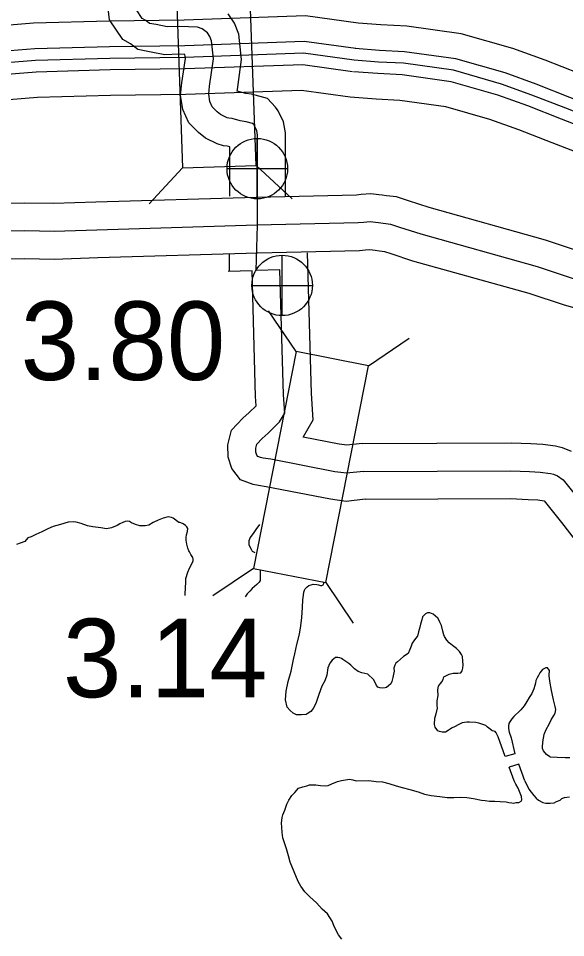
# Model space of a CAD drawing. Extents: x 31699 to 244310, y -8841 to 11474.
# Drawn here: x 95308.6 to 95504.6, y 4462.2 to 4791.7 of the extents above; entities that cross this region are included whole.
import ezdxf

# ---------------------------------------------------------------- set-up
doc = ezdxf.new("R2010")
doc.units = 0
for name, color, linetype in [('B_Logo', 7, 'Continuous'), ('Level 21', 7, 'Continuous'), ('Level 55', 7, 'Continuous'), ('New Level (0)', 7, 'Continuous'), ('R_Draft', 7, 'Continuous'), ('R_XS_EARTHWORK_STAGE1', 7, 'Continuous'), ('S_AREA_CALC', 7, 'Continuous'), ('S_WALL', 7, 'Continuous'), ('S_WALL_ANNOT', 7, 'Continuous')]:
    doc.layers.add(name, color=color, linetype=linetype)

msp = doc.modelspace()

# ---------------------------------------------------------------- linework, layer by layer
at = {"layer": 'B_Logo'}
for points in [[(95394.31, 4717.6), (95394.32, 4749.76), (95394, 4751.49), (95393.36, 4752.8), (95393.21, 4753.2), (95392.93, 4753.59), (95392.52, 4754.05), (95390.17, 4754.64), (95388.03, 4754.98), (95385.21, 4755.76), (95384.01, 4755.86), (95383.4, 4756.04), (95381.04, 4757.17), (95379.88, 4758.14), (95378.09, 4759.96), (95377.23, 4761.87), (95376.82, 4764.46), (95377.13, 4767.41), (95378.49, 4777.15), (95377.83, 4783.62), (95377.18, 4785.2), (95376.34, 4786.45), (95374.5, 4787.93), (95372.75, 4788.54), (95366.28, 4788.81), (95361.89, 4788.67), (95358.01, 4789.42), (95355.59, 4789.88), (95354.23, 4790.91), (95353.01, 4791.61), (95350.92, 4794.75)], [(95428.93, 4776.69), (95410.73, 4779.21), (95368.29, 4777.71), (95341.4, 4777.34), (95314.78, 4776.59), (95287.88, 4774.42), (95256.12, 4771.98), (95237.53, 4770.27), (95220.63, 4767.74), (95182.35, 4765.15), (95161.75, 4763.78), (95143.2, 4762.74), (95123.51, 4762.07), (95105.51, 4760.78), (95091.27, 4760.34), (95076.88, 4760.43), (95060.56, 4760.8), (95046.88, 4761.51), (95032.81, 4762.35), (95025.11, 4763.52), (95016.47, 4765.19), (94992.33, 4769)], [(95671.8, 4700.29), (95659.27, 4704.76), (95640.93, 4711.07), (95619.64, 4718.13), (95600.28, 4725.15), (95579.79, 4732.56), (95563.18, 4738.5), (95541.69, 4745.69), (95522.8, 4752.46), (95504.71, 4759.44), (95492.58, 4764.18), (95481.67, 4768.14), (95464.47, 4773.06), (95446.52, 4775.57), (95437.66, 4776.03), (95428.93, 4776.69)], [(95430.28, 4718.38), (95394.04, 4717.52), (95336.69, 4715.82), (95321.39, 4715.28), (95310.93, 4715.5), (95297.09, 4715.27), (95201.85, 4715.61), (95155.29, 4715.98), (95130.06, 4715.87), (95108.76, 4715.48), (95079.46, 4715.58), (95042.35, 4716.11), (95028.96, 4716.17), (95020.63, 4716.58), (95005.85, 4718.73), (94990.74, 4722.04)], [(95676.95, 4674.08), (95641.72, 4678.91), (95608.09, 4683.23), (95582.09, 4685.75), (95560.8, 4688.8), (95544.39, 4690.74), (95532.84, 4692.35), (95524.89, 4693.89), (95516.54, 4695.89), (95507.11, 4698.47), (95494.52, 4702.61), (95452.85, 4714.28), (95445.29, 4716.75), (95442.01, 4717.84), (95439.27, 4718.13), (95437.67, 4718.37), (95436.6, 4718.48), (95434.6, 4718.72), (95432.21, 4718.54), (95430.28, 4718.38)], [(95432.27, 4629.31), (95426.14, 4628.65), (95424.13, 4628.92), (95421.99, 4629.19), (95399.01, 4633.7), (95396.27, 4634.08), (95395.4, 4634.26), (95394.39, 4634.63), (95394.04, 4635.08), (95393.68, 4636.21), (95393.63, 4637.68), (95393.99, 4639.03), (95395.99, 4641.16), (95398.13, 4643.03), (95402.2, 4647.04), (95404.04, 4650.17), (95403.57, 4656.71), (95402.32, 4701.53), (95393.74, 4701.33), (95394.31, 4717.6)], [(95432.27, 4629.31), (95485.07, 4629.57), (95491.73, 4629.28), (95495.59, 4629.07), (95499.26, 4628.6), (95500.33, 4628.35), (95501.74, 4627.77), (95503.83, 4626.27), (95511.04, 4617.18)]]:
    msp.add_lwpolyline(points, dxfattribs=at)
at = {"layer": 'Level 21'}
for p, q in [((95394.19, 4726.98), (95394.19, 4748.65)), ((95383.35, 4737.82), (95405.02, 4737.82)), ((95403.1, 4685.14), (95403.1, 4706.81)), ((95392.27, 4695.97), (95413.94, 4695.97))]:
    msp.add_line(p, q, dxfattribs=at)
for centre in [(95394.19, 4737.82), (95403.1, 4695.97)]:
    msp.add_circle(centre, 10.83, dxfattribs=at)
at = {"layer": 'Level 55'}
for points in [[(95384.31, 4727.9), (95384.32, 4745.63), (95383.46, 4745.87), (95382.15, 4745.98), (95379.79, 4746.69), (95375.6, 4748.69), (95373.1, 4750.77), (95369.7, 4754.22), (95367.56, 4758.99), (95366.74, 4764.19), (95367.2, 4768.63), (95368.42, 4777.34), (95368.28, 4778.72), (95366.23, 4778.8), (95361.09, 4778.64), (95356.12, 4779.6), (95351.43, 4780.5), (95348.72, 4782.55), (95346, 4784.1), (95341.29, 4791.16), (95340.24, 4799.41)], [(95404.31, 4728.04), (95404.32, 4750.67), (95403.59, 4754.64), (95401.7, 4758.52), (95400.74, 4759.87), (95397.9, 4763), (95392.18, 4764.45), (95390.15, 4764.77), (95387, 4765.64), (95387.05, 4766.2), (95388.56, 4776.97), (95387.63, 4786.07), (95386.05, 4789.93), (95383.79, 4793.29)], [(95384.3, 4701.01), (95384.3, 4707.12)], [(95431.71, 4639.31), (95426.28, 4638.72), (95425.43, 4638.84), (95423.58, 4639.07), (95410.61, 4641.62), (95414.23, 4647.79), (95413.56, 4657.2), (95412.16, 4707.65)], [(95432.83, 4619.31), (95426, 4618.58), (95422.84, 4619.01), (95420.41, 4619.31), (95397.36, 4623.83), (95394.6, 4624.22), (95392.69, 4624.6), (95388.2, 4626.25), (95385.06, 4630.38), (95383.73, 4634.47), (95383.59, 4638.83), (95384.97, 4644.03), (95389.03, 4648.36), (95391.33, 4650.37), (95393.82, 4652.82), (95393.58, 4656.21), (95392.33, 4701.21)], [(95392.33, 4701.21), (95383.75, 4701.01)], [(95431.71, 4639.31), (95485.26, 4639.57), (95492.21, 4639.27), (95496.5, 4639.04), (95501.05, 4638.45), (95503.39, 4637.91), (95506.62, 4636.58)], [(95432.83, 4619.31), (95484.87, 4619.57), (95491.25, 4619.29), (95494.69, 4619.11), (95496.98, 4618.81), (95503.16, 4611.02), (95508.04, 4604.69)]]:
    msp.add_lwpolyline(points, dxfattribs=at)
at = {"layer": 'New Level (0)'}
for points in [[(95430.35, 4789.95), (95411.41, 4792.58), (95367.96, 4791.04), (95341.12, 4790.68), (95314.06, 4789.91), (95286.83, 4787.72), (95255, 4785.26), (95235.93, 4783.51), (95219.19, 4781.01), (95198.43, 4779.6)], [(95663.68, 4717.34), (95645.19, 4723.7), (95624.01, 4730.73), (95604.82, 4737.69), (95584.3, 4745.11), (95567.54, 4751.1), (95546.05, 4758.29), (95527.45, 4764.95), (95509.54, 4771.87), (95497.28, 4776.66), (95485.78, 4780.83), (95467.25, 4786.14), (95447.79, 4788.86), (95438.5, 4789.34), (95430.35, 4789.95)], [(95429.5, 4780.82), (95410.94, 4783.39), (95368.19, 4781.87), (95341.31, 4781.51), (95314.56, 4780.75), (95287.55, 4778.58), (95255.77, 4776.13), (95237.03, 4774.4), (95220.18, 4771.88), (95199.09, 4770.46)], [(95673.19, 4704.22), (95660.65, 4708.69), (95642.26, 4715.01), (95621.01, 4722.07), (95601.7, 4729.07), (95581.2, 4736.48), (95564.54, 4742.44), (95543.05, 4749.63), (95524.26, 4756.36), (95506.22, 4763.32), (95494.05, 4768.08), (95482.95, 4772.1), (95465.34, 4777.15), (95446.92, 4779.73), (95437.92, 4780.19), (95429.24, 4780.84)], [(95428.35, 4772.56), (95410.51, 4775.04), (95368.39, 4773.54), (95341.48, 4773.18), (95315.01, 4772.43), (95288.21, 4770.27), (95256.48, 4767.82), (95238.03, 4766.13), (95221.08, 4763.59), (95199.51, 4762.14)], [(95670.41, 4696.36), (95657.9, 4700.83), (95639.59, 4707.12), (95618.27, 4714.19), (95598.86, 4721.24), (95578.38, 4728.64), (95561.82, 4734.56), (95540.32, 4741.75), (95521.35, 4748.55), (95503.2, 4755.55), (95491.11, 4760.28), (95480.38, 4764.17), (95463.61, 4768.98), (95446.13, 4771.42), (95437.4, 4771.87), (95428.61, 4772.53)], [(95427.51, 4763.43), (95410.04, 4765.85), (95368.61, 4764.38), (95341.67, 4764.01), (95315.51, 4763.27), (95288.93, 4761.13), (95257.25, 4758.69), (95239.13, 4757.02), (95222.06, 4754.47), (95200.16, 4752.99)], [(95667.35, 4687.72), (95654.87, 4692.17), (95636.66, 4698.43), (95615.27, 4705.53), (95595.74, 4712.62), (95575.28, 4720.02), (95558.82, 4725.9), (95537.32, 4733.09), (95518.15, 4739.96), (95499.88, 4747.01), (95487.88, 4751.7), (95477.55, 4755.45), (95461.7, 4759.99), (95445.25, 4762.29), (95436.82, 4762.72), (95427.51, 4763.43)]]:
    msp.add_lwpolyline(points, dxfattribs=at)
at = {"layer": 'R_Draft'}
for points in [[(95368.51, 4609.96), (95367.7, 4610.47), (95366.82, 4610.91), (95366.42, 4611.03), (95366.15, 4611.02), (95364.11, 4612.5), (95363.43, 4612.81), (95362.23, 4612.98), (95360.51, 4612.59), (95358.67, 4611.86), (95356.9, 4610.94), (95355.32, 4610.09), (95354.07, 4609.85), (95352.13, 4609.86), (95350.52, 4610.27), (95349.11, 4610.83), (95348.36, 4611.41), (95347.62, 4611.52), (95346.83, 4611.36), (95345.97, 4611), (95344.99, 4610.51), (95344.01, 4609.94), (95341.97, 4609.08), (95340.18, 4608.75), (95338.18, 4609.03), (95335.3, 4609.4), (95333.36, 4609.81), (95331.14, 4610.61), (95329.32, 4611.09), (95328.32, 4611.26), (95326.46, 4611.14), (95323.75, 4610.32), (95321.11, 4609.57), (95319.21, 4608.77), (95316.97, 4607.7), (95314.87, 4606.7), (95313.17, 4605.85), (95312.05, 4605.55), (95310.95, 4604.24), (95309.24, 4603.65), (95307.93, 4603.08)], [(95368.4, 4584.83), (95368.52, 4588.03), (95368.55, 4589.17), (95368.56, 4590.97), (95369.29, 4593.2), (95369.91, 4594.69), (95370.8, 4596.19), (95371.23, 4597.27), (95371.21, 4597.87), (95371.06, 4598.47), (95370.43, 4599.52), (95369.87, 4600.44), (95369.73, 4600.84), (95369.36, 4601.76), (95368.99, 4603.22), (95368.68, 4604.68), (95368.71, 4605.62), (95368.88, 4606.63), (95369.25, 4607.78), (95369.28, 4608.85), (95369, 4609.44), (95368.51, 4609.96)], [(95394.93, 4610.29), (95393.73, 4608.46), (95392.9, 4607.44), (95391.62, 4605.66), (95391.19, 4604.37), (95391.17, 4603.04), (95391.95, 4601.39), (95392.37, 4600.73), (95393.35, 4600.25)], [(95395.18, 4593.83), (95395.26, 4591.19), (95395.22, 4590.19), (95394.91, 4589.65), (95394, 4588.75), (95392.38, 4587.36), (95391.54, 4586.4), (95390.58, 4585.43), (95389.91, 4584.39)], [(95433.8, 4556.65), (95431.67, 4557.15), (95430.39, 4557.64), (95429.03, 4558.54), (95428.27, 4559.32), (95427.65, 4559.9), (95426.97, 4560.41), (95426.22, 4560.99), (95424.79, 4561.95), (95424.32, 4562.2), (95423.78, 4562.52), (95423.11, 4562.63), (95422.18, 4562.61), (95421, 4561.7), (95420.17, 4560.6), (95419.49, 4558.91), (95419.11, 4556.23), (95418.44, 4554.27), (95417.3, 4552.29), (95416.26, 4549.32), (95415.22, 4546.08), (95414.21, 4544.31), (95413.32, 4543.21), (95412.08, 4542.37), (95411.68, 4542.22), (95410.09, 4542.04), (95408.29, 4542.05), (95407.07, 4542.68), (95405.98, 4543.59), (95404.94, 4544.76), (95404.33, 4547.48), (95404.5, 4550.56), (95405.26, 4553.99), (95406.34, 4557.77), (95407.21, 4561.88), (95407.68, 4563.96), (95408.38, 4567.33), (95409.26, 4571.03), (95409.77, 4573.92), (95410.15, 4576.94), (95410.44, 4580.56), (95410.49, 4583.24), (95410.7, 4584.92), (95410.87, 4586.06), (95411.05, 4586.73), (95411.3, 4587.21), (95412.08, 4587.9), (95412.66, 4588.39), (95413.45, 4588.68), (95414.24, 4588.84), (95415.58, 4588.75), (95416.18, 4588.63), (95416.85, 4588.45), (95417.32, 4588.46), (95417.78, 4588.61), (95418.03, 4589.16), (95417.91, 4589.61)], [(95454.42, 4578.21), (95453.43, 4577.2), (95453.12, 4576.12), (95452.61, 4574.58), (95452.43, 4573.51), (95451.99, 4571.83), (95451.55, 4570.29), (95451.49, 4570.09), (95450.57, 4568.94), (95449.73, 4567.79), (95449.28, 4566.65), (95448.9, 4565.51), (95448.19, 4564.1), (95446.61, 4562.94), (95445.49, 4561.98), (95444.38, 4561.1), (95443.85, 4560.62), (95443.46, 4559.88), (95443.15, 4558.74), (95443.23, 4557.67), (95443.05, 4556.67), (95442.74, 4555.46), (95442.36, 4553.99), (95441.98, 4553.18), (95441.19, 4552.44), (95440.46, 4551.89), (95440, 4551.75), (95439.14, 4551.6), (95438.07, 4551.72), (95437.33, 4552.04), (95436.93, 4552.57), (95436.3, 4553.89), (95435.82, 4554.75), (95433.8, 4556.65)], [(95483.05, 4527.08), (95480.44, 4534.19), (95479.88, 4535.38), (95479.88, 4535.45), (95479.68, 4535.78), (95479.41, 4536.11), (95478.94, 4536.16), (95478.34, 4536.29), (95477.6, 4536.88), (95476.72, 4537.6), (95476.11, 4538.19), (95474.64, 4538.76), (95473.57, 4539.08), (95472.5, 4539.26), (95470.23, 4539.49), (95469.23, 4539.48), (95467.64, 4539.18), (95466.12, 4538.43), (95465.06, 4537.94), (95463.74, 4537.25), (95463.28, 4536.98), (95462.62, 4536.5), (95461.57, 4535.88), (95460.37, 4535.8), (95459.5, 4536.05), (95458.9, 4536.37), (95457.88, 4537.69), (95457.73, 4538.56), (95457.82, 4540.83), (95458.26, 4542.37), (95458.7, 4544.44), (95458.68, 4545.38), (95458.65, 4547.11), (95458.95, 4549.05), (95458.92, 4551.06), (95459.17, 4552.39), (95459.82, 4553.34), (95460.34, 4553.95), (95460.73, 4554.69), (95461.04, 4555.63), (95461.77, 4556.04), (95462.96, 4556.59), (95464.35, 4557.02), (95466.01, 4556.98), (95467.08, 4557.06), (95467.6, 4557.8), (95467.78, 4558.74), (95467.9, 4559.95), (95467.88, 4561.28), (95467.71, 4562.95), (95467.37, 4563.74), (95466.69, 4564.8), (95465.6, 4565.78), (95464.12, 4566.89), (95462.91, 4567.87), (95462.09, 4568.86), (95461.27, 4570.12), (95461.06, 4570.71), (95460.71, 4572.11), (95460.21, 4574.04), (95460, 4574.57), (95459.59, 4575.29), (95459.04, 4576.55), (95458.83, 4576.75), (95458.09, 4577.47), (95457.21, 4578.19), (95456.01, 4578.57), (95455.14, 4578.63), (95454.42, 4578.21)], [(95496.63, 4533.05), (95496.81, 4534.25), (95496.93, 4535.12), (95497.06, 4535.39), (95497.7, 4536.8), (95498.74, 4538.76), (95499.51, 4540.24), (95500.1, 4541.18), (95500.48, 4541.86), (95500.94, 4542.66), (95501.12, 4544), (95500.96, 4545.07), (95500.33, 4547.46), (95500.25, 4547.99), (95499.54, 4550.78), (95498.95, 4554.18), (95498.72, 4556.11), (95498.77, 4556.84), (95498.83, 4557.51), (95498.89, 4557.78), (95498.82, 4557.98), (95498.68, 4558.31), (95498.41, 4558.57), (95498.14, 4558.97), (95497.87, 4558.97), (95497.61, 4558.96), (95496.42, 4558.34), (95495.9, 4557.73), (95495.44, 4557.06), (95494.92, 4556.18), (95494.41, 4555.31), (95493.95, 4554.36), (95493.84, 4553.36), (95493.65, 4552.56), (95493.21, 4551.35), (95492.5, 4549.73), (95491.59, 4548.25), (95490.81, 4546.9), (95489.78, 4545.29), (95488.6, 4543.86), (95487.88, 4543.12), (95486.57, 4541.96), (95486.11, 4541.42), (95485.39, 4540.61), (95484.87, 4539.87), (95484.61, 4539.53), (95484.29, 4538.92), (95484.17, 4538.12), (95484.18, 4537.12), (95484.47, 4535.85), (95485.1, 4533.86)], [(95485.1, 4533.86), (95486.46, 4528.08), (95483.05, 4527.08)], [(95506.13, 4526.6), (95504.46, 4526.7), (95501.6, 4526.72), (95499.26, 4526.95), (95499, 4527.01), (95497.85, 4527.8), (95496.76, 4529.18), (95496.35, 4530.04), (95496.34, 4530.78), (95496.63, 4533.05)], [(95490.08, 4518.46), (95487.85, 4524.36), (95484.45, 4523.27)], [(95434.15, 4518.48), (95436.76, 4518.12), (95439.02, 4518.03), (95441.3, 4517.4), (95443.97, 4516.64), (95446.11, 4516.01), (95448.85, 4515.25), (95451.8, 4514.43), (95454.14, 4513.67), (95456.48, 4513.17), (95459.55, 4512.76), (95462.22, 4512.47), (95464.61, 4512.44), (95466.88, 4512.54), (95469.21, 4512.45), (95471.61, 4512.09), (95474.55, 4511.53), (95475.88, 4511.35), (95477.35, 4511.18), (95479.28, 4511.08), (95481.22, 4510.97), (95483.41, 4510.94), (95484.35, 4510.69), (95485.35, 4510.51), (95486.15, 4510.45), (95486.88, 4510.6), (95487.88, 4510.68), (95488.74, 4511.1), (95488.93, 4511.57), (95488.84, 4512.83), (95487.66, 4515.75), (95486.84, 4517.21), (95486.22, 4518.46), (95484.45, 4523.27)], [(95424.48, 4461.65), (95423.3, 4463.22), (95422.45, 4464.8), (95421.66, 4466.51), (95421.01, 4468.16), (95419.4, 4470.72), (95417.49, 4472.47), (95415.42, 4474.68), (95413.02, 4476.81), (95411.24, 4478.63), (95409.84, 4480.72), (95408.86, 4482.3), (95405.98, 4489.3), (95405.38, 4491.55), (95404.71, 4494), (95404.05, 4495.86), (95403.38, 4497.97), (95403.06, 4499.84), (95403, 4501.77), (95402.89, 4503.24), (95403.09, 4505.25), (95403.33, 4506.2), (95404.08, 4507.89), (95404.74, 4510.05), (95405.5, 4511.48), (95406.58, 4513.18), (95407.61, 4514.22), (95408.96, 4515.8), (95410.48, 4516.25), (95411.93, 4516.62), (95412.92, 4516.92), (95413.85, 4517.02), (95415.19, 4516.93), (95416.79, 4516.71), (95418.8, 4516.57), (95419.59, 4516.79), (95420.9, 4517.37), (95422.94, 4518.23), (95424.33, 4518.48), (95427.18, 4519.03), (95428.45, 4518.8), (95429.66, 4518.37), (95434.15, 4518.48)], [(95490.08, 4518.46), (95491.53, 4515.48), (95492.35, 4514.36), (95493.3, 4513.17), (95494.05, 4512.25), (95494.99, 4511.47), (95496.47, 4510.62), (95497.6, 4510.37), (95499.14, 4510.4), (95500.53, 4510.55), (95501.39, 4510.97), (95502.65, 4511.52), (95503.3, 4512.07), (95504.29, 4512.48), (95506.02, 4512.65)]]:
    msp.add_lwpolyline(points, dxfattribs=at)
at = {"layer": 'R_XS_EARTHWORK_STAGE1'}
for p, q in [((95367.41, 4738.05), (95355.42, 4725.17)), ((95393.79, 4738.99), (95406.67, 4726.99)), ((95408.07, 4672.28), (95398.26, 4686.88)), ((95433.98, 4667.2), (95448.59, 4677.01)), ((95392.83, 4594.56), (95378.22, 4584.74)), ((95418.74, 4589.48), (95428.55, 4574.87))]:
    msp.add_line(p, q, dxfattribs=at)
for points in [[(95393.79, 4738.99), (95390.98, 4818.14), (95364.6, 4817.2), (95367.41, 4738.05)], [(95418.74, 4589.48), (95433.98, 4667.2), (95408.07, 4672.28), (95392.83, 4594.56)]]:
    msp.add_lwpolyline(points, close=True, dxfattribs=at)
at = {"layer": 'S_AREA_CALC'}
for points in [[(95429.74, 4728.37), (95393.78, 4727.52), (95336.37, 4725.82), (95321.32, 4725.29), (95310.95, 4725.5), (95297.02, 4725.27), (95201.91, 4725.61), (95155.31, 4725.98), (95129.95, 4725.87), (95108.69, 4725.48), (95079.55, 4725.58), (95042.44, 4726.11), (95029.23, 4726.16), (95021.6, 4726.54), (95007.64, 4728.57), (94992.55, 4731.88)], [(95673.64, 4684.63), (95643.04, 4688.82), (95609.21, 4693.17), (95583.28, 4695.68), (95562.09, 4698.72), (95545.66, 4700.66), (95534.49, 4702.22), (95527.01, 4703.67), (95519.02, 4705.58), (95509.99, 4708.05), (95497.43, 4712.18), (95455.76, 4723.85), (95448.41, 4726.25), (95444.12, 4727.67), (95440.54, 4728.05), (95438.96, 4728.29), (95437.73, 4728.42), (95434.83, 4728.76), (95431.42, 4728.51), (95429.74, 4728.37)], [(95430.83, 4708.39), (95394.31, 4707.53), (95337.02, 4705.83), (95321.47, 4705.28), (95310.91, 4705.49), (95297.15, 4705.27), (95201.79, 4705.61), (95155.28, 4705.98), (95130.17, 4705.87), (95108.84, 4705.48), (95079.37, 4705.58), (95042.26, 4706.11), (95028.7, 4706.17), (95019.66, 4706.61), (95004.05, 4708.88), (94988.92, 4712.19)], [(95675.07, 4664.24), (95640.4, 4669), (95606.97, 4673.3), (95580.89, 4675.82), (95559.5, 4678.89), (95543.11, 4680.82), (95531.2, 4682.49), (95522.78, 4684.12), (95514.05, 4686.2), (95504.23, 4688.9), (95491.61, 4693.04), (95449.95, 4704.7), (95442.17, 4707.25), (95439.89, 4708), (95438, 4708.2), (95436.39, 4708.45), (95435.48, 4708.55), (95434.38, 4708.67), (95432.99, 4708.57), (95430.83, 4708.39)]]:
    msp.add_lwpolyline(points, dxfattribs=at)

# ---------------------------------------------------------------- texts
at = {"layer": 'S_WALL'}
msp.add_text('3.14', height=28.16, dxfattribs=at).set_placement((95324.59, 4548.36))
at = {"layer": 'S_WALL_ANNOT'}
msp.add_text('3.80', height=28.16, dxfattribs=at).set_placement((95309.44, 4662.06))

doc.saveas('drawing.dxf')
